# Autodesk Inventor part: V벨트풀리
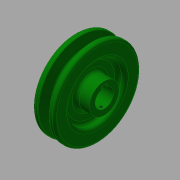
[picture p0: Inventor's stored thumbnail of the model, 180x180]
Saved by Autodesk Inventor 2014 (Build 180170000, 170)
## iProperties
Created: 2015-11
Part Number: V벨트풀리
Material: 강철, 탄소
Document SubType Name: Modeling
Designer: mduedu
Density: 1 g/cm^3
Appearance: Dark Green
Author: mduedu
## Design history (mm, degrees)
sketch "스케치1"
  geometry: L1 (-9.5, 0)-(9.5, 0); L2 (0, 0)-(0, 37.7); L3 (-4.825, 37.7)-(-9.5, 37.7); L4 (-9.5, 37.7)-(-9.5, 0); L5 (0, 28.7)-(-2.074, 28.7); L6 (-2.074, 28.7)-(-4.825, 37.7); L7 (4.825, 37.7)-(9.5, 37.7); L8 (9.5, 37.7)-(9.5, 0); L9 (0, 28.7)-(2.074, 28.7); L10 (2.074, 28.7)-(4.825, 37.7); L11 (-9.5, 35)-(9.5, 35); 3 further points
  constraints: 22 end point, 7 point on line, 4 perpendicular, 3 symmetric about line, 1 coincident, 1 horizontal, 1 horizontal alignment, 1 midpoint, 1 vertical
  dimensions: "d0" = 19 distance of L1.start L1.end; "d2" = 75.4 diameter of L2.end L1 (derived); "d3" = 34 deg angle of L10 L6; "d4" = 6.3 distance between parallel lines of L11 L9; "d5" = 2.7 distance between parallel lines of L7 L11; "d6" = 8 distance of point (4, 35) point (-4, 35); "d7" = 70 diameter of L11 L1
revolve "회전1" sketch "스케치1" stored, may be unused: angle "d8" = 90 deg
sketch "스케치2"
  geometry: C1 r 24 at (0, 0); C2 r 13 at (0, 0); 1 further point
  constraints: 2 centre point, 2 coincident
  dimensions: "d9" = 48 diameter of C1; "d10" = 26 diameter of C2
extrude "돌출1" cut sketch "스케치2" distance "d11" = 6; taper "d12" = 0 deg
extrude "돌출3" join sketch "스케치2" distance "d37" = 6; taper "d38" = 0 deg
fillet "모깎기1" dims "d13" = 3
fillet "모깎기2" dims "d14" = 3
fillet "모깎기3" dims "d15" = 1, "d16" = 0.5, "d17" = 2
hole "구멍1" diameter "d20" = 16; stored, may be unused: countersink angle "d24" = 90 deg, drill point angle "d26" = 118 deg; dims "d21" = 6, "d22" = 4, "d23" = 2, "d25" = 8, "d53" = 10, "d54" = 10
sketch "스케치3"
  geometry: L1 (-2.5, 0)-(2.5, 0); L2 (2.5, 0)-(2.5, 10.3); L3 (2.5, 10.3)-(-2.5, 10.3); L4 (-2.5, 10.3)-(-2.5, 0); 2 further points
  constraints: 8 end point, 2 parallel, 1 coincident, 1 horizontal, 1 midpoint, 1 perpendicular
  dimensions: "d27" = 5 distance of L2.end L3.end; "d29" = 10.3 distance of L3.end L1.start
extrude "돌출2" cut sketch "스케치3" stored distance "d30" = 6; taper "d31" = 0 deg
node "작업 평면1"
sketch "스케치4"
  geometry: L1 (19, -27)-(19, 27) reference; 2 further points
  constraints: 1 horizontal alignment
  dimensions: "d52" = 22 distance from line of L1 point (-3, 0)
hole "구멍2" sketch "스케치4" at (-3, 0) diameter "d42" = 2.459; stored, may be unused: countersink angle "d46" = 90 deg, drill point angle "d48" = 118 deg; dims "d43" = 6, "d44" = 4, "d45" = 2, "d47" = 8
node "솔리드1"
mirror "대칭1"
